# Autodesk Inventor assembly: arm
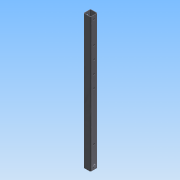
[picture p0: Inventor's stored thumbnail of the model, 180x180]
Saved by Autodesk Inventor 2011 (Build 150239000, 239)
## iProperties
Created: 2020-12
Part Number: arm
Document SubType Name: Assembly
Designer: PC
Author: PC
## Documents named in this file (3)
- C:\Users\PC\Documents\Inventor\workshop-crane-powered-by-drill\arm.iam
- C:\Users\PC\Documents\Inventor\workshop-crane-powered-by-drill\6_brazo.iam
- C:\Users\PC\Documents\Inventor\workshop-crane-powered-by-drill\arm\Design Accelerator\Bolted Connection1.iam
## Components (2 placed, 2 different names)
1. 6_brazo:1 [sub-assembly] — Mate:1, Mate:2
2. Bolted Connection:1 [sub-assembly] — Mate:1, Mate:2
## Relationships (2: Mate 2)
- Mate:1: 6_brazo:1 ↔ Bolted Connection:1
- Mate:2: 6_brazo:1 ↔ Bolted Connection:1
